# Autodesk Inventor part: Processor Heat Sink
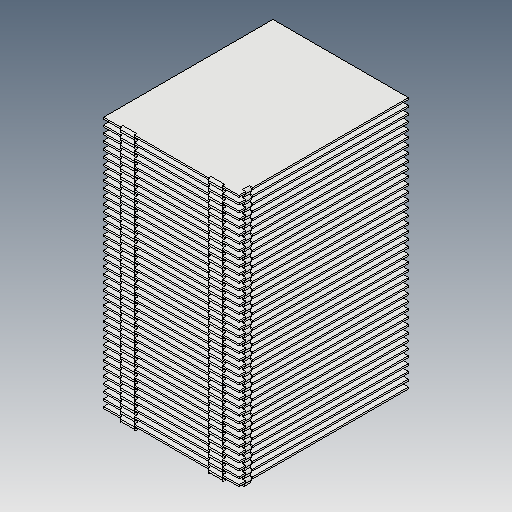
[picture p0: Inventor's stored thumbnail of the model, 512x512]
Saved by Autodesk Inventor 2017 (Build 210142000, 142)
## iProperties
Created: 2005-11
Part Number: Processor Heat Sink
Material: Generic
Document SubType Name: Modeling
Designer: DanielSeverino
Density: 1 g/cm^3
Appearance: Default
Author: DanielSeverino
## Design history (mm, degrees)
feature "Solid1"
body "Solid2"
